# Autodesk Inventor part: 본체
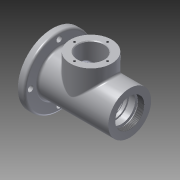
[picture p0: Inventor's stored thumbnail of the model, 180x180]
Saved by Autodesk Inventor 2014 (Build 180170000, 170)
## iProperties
Created: 2016-08
Part Number: 본체
Material: 알루미늄 6061
Document SubType Name: Modeling
Designer: owner
Density: 2.71 g/cm^3
Appearance: 알루미늄 - 평지
Mass: 728.386 g
Surface Area: 615.665 cm^2
Volume: 268.777 cm^3
Author: owner
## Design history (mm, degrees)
sketch "스케치1"
  geometry: L1 (0, 0)-(-57.5, 0); L2 (-57.5, 0)-(-57.5, 31); L3 (0, 0)-(57.5, 0); L4 (57.5, 0)-(57.5, 31); L5 (57.5, 31)-(54.5, 31); L6 (57.5, 0)-(54.5, 0); L7 (54.5, 31)-(57.5, 31); L8 (57.5, 0)-(57.5, 21); L9 (43.5, 0)-(36.2, 0); L10 (43.5, 0)-(42.8, 0); L11 (36.2, 0)-(33.5, 0); L12 (-44.5, 50)-(-44.5, 31); L13 (-54.5, 50)-(-44.5, 50); L14 (-54.5, 31)-(-54.5, 50); L15 (44.5, 31)-(54.5, 31); L16 (-57.5, 31)-(-54.5, 31); L17 (-44.5, 31)-(44.5, 31)
  constraints: 34 end point, 6 point on line, 3 perpendicular, 1 horizontal
revolve "회전1" sketch "스케치1" stored, may be unused: angle "d19" = 90 deg
sketch "스케치2"
  geometry: L1 (57.5, 0)-(57.5, 21); L2 (57.5, 0)-(43.5, 0); L3 (43.5, 0)-(36.2, 0); L4 (43.5, 0)-(42.8, 0); L5 (36.2, 0)-(33.5, 0); L6 (-45.5, 0)-(-48.5, 0); L7 (-57.5, 0)-(-36.5, 0); L8 (-57.5, 0)-(-31.5, 0); L9 (0.391, 0)-(-18.609, 0); L10 (19.391, 0)-(0.391, 0); L11 (0.391, 0)-(-29.609, 0); L12 (-57.5, 0)-(-31.5, 0); L13 (0.391, 0)-(19.391, 0); L14 (0.391, 0)-(-18.609, 0); L15 (-31.5, 0)-(28.5, 0); L16 (-57.5, 0)-(-1.5, 0); L17 (-45.491, 16.711)-(-57.5, 21); L18 (-28.2, 17.5)-(-17.5, 17.5); L19 (-17.5, 23)-(-17.5, 17.5); L20 (0, 26)-(-14.5, 26); L21 (-43.5, 12.904)-(-43.5, 13.886); L22 (-42.8, 12.5)-(-43.5, 12.904); L23 (-36.5, 12.5)-(-42.8, 12.5); L24 (-36.2, 10)-(-36.2, 12.2); L25 (-33.5, 10)-(-33.5, 13.5); L26 (-33.5, 10)-(-36.2, 10); L27 (-28.5, 16.5)-(-28.5, 17.2); L28 (-30.5, 16.5)-(-28.5, 16.5); L29 (31.5, 17.5)-(20.8, 17.5); L30 (20.5, 23)-(20.5, 17.8); L31 (1.5, 26)-(17.5, 26); L32 (57.5, 21)-(48.5, 21); L33 (45.5, 21)-(45.5, 20); L34 (33.25, 17.5)-(36.5, 17.5); L35 (33.25, 18.5)-(33.25, 17.5); L36 (31.5, 17.5)-(31.5, 18.5); L37 (31.5, 18.5)-(33.25, 18.5); L38 (36.5, 17.5)-(36.5, 20); L39 (36.5, 20)-(45.5, 20); L40 (48.5, 24)-(45.5, 24); L41 (48.5, 21)-(48.5, 24); L42 (45.5, 24)-(45.5, 21); L43 (1.5, 26)-(0, 26); L44 (-57.5, 21)-(-57.5, 0); L45 (57.5, 0)-(-28.5, 0); A1 r 3 centre (-46.5, 13.886) between (-43.5, 13.886) and (-45.491, 16.711); A2 r 0.3 centre (-36.5, 12.2) between (-36.2, 12.2) and (-36.5, 12.5); A3 r 3 centre (-30.5, 13.5) between (-30.5, 16.5) and (-33.5, 13.5); A4 r 0.3 centre (20.8, 17.8) between (20.5, 17.8) and (20.8, 17.5); A5 r 3 centre (-14.5, 23) between (-14.5, 26) and (-17.5, 23); A6 r 3 centre (17.5, 23) between (20.5, 23) and (17.5, 26); A7 r 0.3 centre (-28.2, 17.2) between (-28.2, 17.5) and (-28.5, 17.2); 6 further points
  constraints: 90 end point, 14 point on circle, 8 point on line, 7 centre point, 6 tangent, 4 horizontal, 2 perpendicular, 1 equal radius, 1 midpoint, 14 other
revolve "회전2" sketch "스케치2" stored, may be unused: angle "d62" = 90 deg
node "작업 평면1"
sketch "스케치4"
  geometry: L1 (57.5, -31)-(57.5, 0); C1 r 30 at (1.5, 0); 5 further points
  constraints: 2 end point, 1 centre point
sketch "스케치5"
  geometry: C1 r 4 at (-41.5, 0); C2 r 4 at (41.5, 0); C3 r 4 at (0, 41.5); C4 r 4 at (0, -41.5)
  constraints: 4 centre point
extrude "돌출2" cut sketch "스케치5" distance "d104" = 10; taper "d105" = 0 deg
feature "스레드2" dims "d106" = 10, "d107" = 0
fillet "모깎기1" dims "d108" = 3
node "작업 평면2"
extrude "돌출3" join sketch "스케치4" stored distance "d119" = 10; taper "d120" = 0 deg
hole "구멍4" sketch "스케치4" diameter "d121" = 3.242; stored, may be unused: countersink angle "d125" = 90 deg, drill point angle "d127" = 118 deg; dims "d122" = 8, "d123" = 4, "d124" = 2, "d126" = 10
hole "구멍5" diameter "d130" = 38; stored, may be unused: countersink angle "d134" = 90 deg, drill point angle "d136" = 0 deg; dims "d128" = 10, "d129" = 10, "d131" = 8, "d132" = 4, "d133" = 2, "d135" = 60
node "작업 평면3"
sketch "스케치7"
  geometry: L1 (-31.5, 49)-(28.5, 49) reference; L2 (-57.5, 31)-(-57.5, -31) reference; L3 (-1.5, 48.137)-(-1.5, 38.137); 2 further points
  constraints: 2 end point, 1 other
feature "엠보싱2" sketch "스케치7" dims "d141" = 0.5, "d142" = 0
fillet "모깎기2" dims "d143" = 3
chamfer "모따기2" distance "d144" = 1; stored, may be unused: second distance "d145" = 2, angle "d146" = 45 deg
node "솔리드1"
other parameters: "d64" = 49
